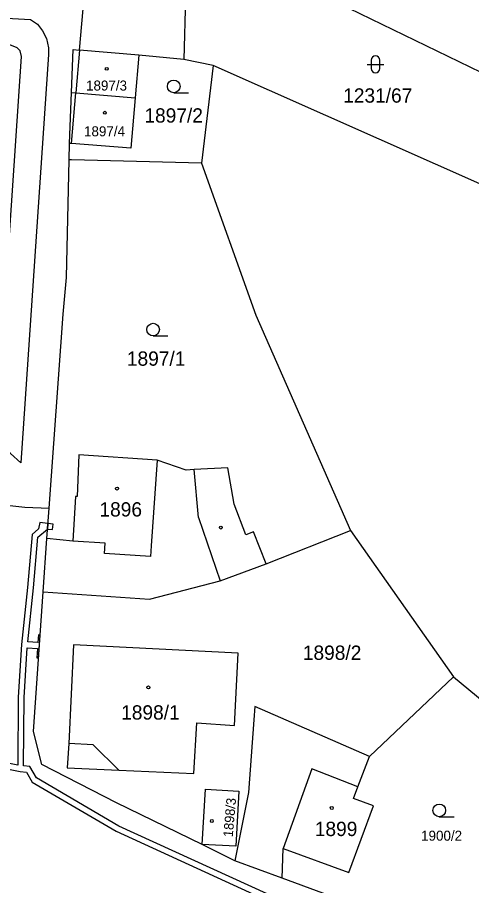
# Model space of a CAD drawing. Extents: x -869103 to -863415, y -1015889 to -1012477.
# Drawn here: x -866081.7 to -866027.8, y -1014098.2 to -1013995 of the extents above; entities that cross this region are included whole.
import ezdxf

# ---------------------------------------------------------------- set-up
doc = ezdxf.new("R2010")
doc.units = 0
for name, color, linetype in [('Hranice parcel', 7, 'Continuous'), ('Parcelní čísla', 7, 'Continuous'), ('Vnitřní kresba', 7, 'Continuous'), ('Věcná břemena k části', 7, 'Continuous'), ('Značky budov', 7, 'Continuous'), ('Značky kultur', 7, 'Continuous')]:
    doc.layers.add(name, color=color, linetype=linetype)

msp = doc.modelspace()

# ---------------------------------------------------------------- linework, layer by layer
at = {"layer": 'Hranice parcel'}
for p, q in [((-866061.52, -1013984.57), (-866061.96, -1014000.03)), ((-866061.52, -1013984.57), (-866023.9, -1014002.91)), ((-866074.34, -1013998.92), (-866073.68, -1013991.28)), ((-866067.3, -1013999.52), (-866074.34, -1013998.92)), ((-866067.3, -1013999.52), (-866067.73, -1014004.57)), ((-866061.96, -1014000.03), (-866067.3, -1013999.52)), ((-866058.47, -1014000.73), (-866061.96, -1014000.03)), ((-866058.47, -1014000.73), (-866059.85, -1014012.35)), ((-866019.25, -1014018.15), (-866058.47, -1014000.73)), ((-866075.52, -1014010.01), (-866075.29, -1014003.97)), ((-866075.29, -1014003.97), (-866074.78, -1014004.01)), ((-866074.78, -1014004.01), (-866067.73, -1014004.57)), ((-866075.57, -1014011.96), (-866075.52, -1014010.01)), ((-866075.3, -1014010.03), (-866075.52, -1014010.01)), ((-866077.96, -1014053.35), (-866076.3, -1014030.31)), ((-866084.83, -1014052.8), (-866080.86, -1014053.22)), ((-866080.86, -1014053.22), (-866077.96, -1014053.35)), ((-866078.22, -1014056.97), (-866077.96, -1014053.35)), ((-866052.18, -1014059.97), (-866042.17, -1014056.01)), ((-866042.17, -1014056.01), (-866029.91, -1014073.39)), ((-866078.65, -1014063.29), (-866078.22, -1014056.97)), ((-866029.91, -1014073.39), (-866039.91, -1014082.84)), ((-866029.91, -1014073.39), (-866022.28, -1014079.75)), ((-866041.28, -1014086.47), (-866039.91, -1014082.84)), ((-866050.27, -1014097.31), (-866050.15, -1014093.78)), ((-866050.15, -1014093.78), (-866042.37, -1014096.65)), ((-866050.27, -1014097.31), (-866055.88, -1014095.24))]:
    msp.add_line(p, q, dxfattribs=at)
for points in [[(-866086.37, -1013994.34), (-866086.2, -1013994.7), (-866085.86, -1013994.95), (-866080.16, -1013995.28), (-866079.34, -1013995.84), (-866078.76, -1013996.61), (-866078.28, -1013997.55), (-866078.04, -1013998.64), (-866078.04, -1013999.43), (-866081.32, -1014047.95), (-866082.54, -1014046.85), (-866083.4, -1014046.21), (-866084.37, -1014045.66), (-866081.25, -1013999.67), (-866081.41, -1013999.02), (-866081.75, -1013998.65), (-866082.62, -1013998.29), (-866090.88, -1013997.79), (-866094.03, -1013993.9)], [(-866075.29, -1014003.97), (-866075.1, -1013998.86), (-866074.34, -1013998.92)], [(-866067.73, -1014004.57), (-866068.24, -1014010.55), (-866075.3, -1014010.03)], [(-866076.3, -1014030.31), (-866075.89, -1014025.95), (-866075.57, -1014011.96)], [(-866059.85, -1014012.35), (-866075.3, -1014011.97), (-866075.57, -1014011.96)], [(-866059.85, -1014012.35), (-866053.39, -1014030.4), (-866042.17, -1014056.01)], [(-866065.12, -1014047.66), (-866074.42, -1014047.01), (-866074.61, -1014051.97), (-866074.81, -1014051.96), (-866075.12, -1014057.26), (-866078.22, -1014056.97)], [(-866052.18, -1014059.97), (-866053.68, -1014056.17), (-866054.6, -1014056.53), (-866055.98, -1014052.86), (-866056.71, -1014048.57), (-866060.72, -1014048.77), (-866061.69, -1014048.82), (-866065.12, -1014047.66)], [(-866078.65, -1014063.29), (-866066.03, -1014064.14), (-866057.64, -1014061.97), (-866052.18, -1014059.97)], [(-866055.88, -1014095.24), (-866059.78, -1014093.3), (-866069.96, -1014088.36), (-866078.83, -1014083.8), (-866079.8, -1014079.9), (-866078.65, -1014063.29)], [(-866060.43, -1014078.84), (-866055.94, -1014079.17), (-866055.5, -1014070.59), (-866075.06, -1014069.59), (-866075.63, -1014081.32), (-866075.8, -1014084.2), (-866069.66, -1014084.49), (-866060.76, -1014084.89), (-866060.43, -1014078.84)], [(-866039.91, -1014082.84), (-866053.54, -1014076.93), (-866053.65, -1014078.48)], [(-866053.65, -1014078.48), (-866054.28, -1014087.14), (-866055.88, -1014095.24)], [(-866055.42, -1014086.97), (-866055.78, -1014093.52), (-866059.78, -1014093.3), (-866059.4, -1014086.73), (-866055.42, -1014086.97)], [(-866042.37, -1014096.65), (-866039.44, -1014088.71), (-866041.81, -1014087.83), (-866041.28, -1014086.47)], [(-866018.26, -1014107.1), (-866024.51, -1014106.26), (-866028.71, -1014105.27), (-866050.27, -1014097.31)]]:
    msp.add_lwpolyline(points, dxfattribs=at)
at = {"layer": 'Vnitřní kresba'}
for p, q in [((-866074.34, -1013998.92), (-866074.78, -1014004.01)), ((-866075.3, -1014010.03), (-866074.78, -1014004.01)), ((-866065.12, -1014047.66), (-866065.84, -1014057.81)), ((-866060.22, -1014054.45), (-866060.72, -1014048.77)), ((-866060.22, -1014054.45), (-866057.64, -1014061.97)), ((-866071.31, -1014057.49), (-866075.12, -1014057.26)), ((-866071.38, -1014058.73), (-866071.31, -1014057.49)), ((-866065.84, -1014057.81), (-866065.92, -1014059.08)), ((-866065.92, -1014059.08), (-866071.38, -1014058.73)), ((-866072.74, -1014081.45), (-866075.63, -1014081.32)), ((-866069.66, -1014084.49), (-866072.74, -1014081.45)), ((-866046.75, -1014084.34), (-866050.15, -1014093.78)), ((-866041.28, -1014086.47), (-866046.75, -1014084.34))]:
    msp.add_line(p, q, dxfattribs=at)
at = {"layer": 'Věcná břemena k části'}
for points in [[(-866052.07, -1014099.17), (-866069.66, -1014091.12), (-866079.44, -1014085.4), (-866080.24, -1014084.05), (-866080.98, -1014083.98), (-866080.92, -1014075.83), (-866080.55, -1014069.94), (-866079.33, -1014070.02), (-866079.42, -1014071.14), (-866079.2, -1014071.17), (-866079.01, -1014068.43), (-866079.21, -1014068.41), (-866079.28, -1014069.32), (-866080.49, -1014069.24), (-866079.83, -1014062.82), (-866079.29, -1014056.8), (-866078.14, -1014055.85), (-866078.09, -1014055.17), (-866079.06, -1014055.05), (-866079.2, -1014055.79), (-866079.97, -1014056.46), (-866080.53, -1014062.76), (-866081.23, -1014069.53), (-866081.62, -1014075.81), (-866081.68, -1014083.88), (-866086.03, -1014083.02)], [(-866138.85, -1014099.9), (-866126.98, -1014101.57), (-866123.49, -1014101.89), (-866116.37, -1014102.66), (-866092.66, -1014105.81), (-866088.56, -1014106.7), (-866088.26, -1014107.08), (-866088.42, -1014110.08), (-866088.97, -1014110.12), (-866089.05, -1014110.81), (-866088.22, -1014110.98), (-866087.64, -1014110.46), (-866087.46, -1014106.98), (-866087.55, -1014106.39), (-866088.27, -1014105.23), (-866087.8, -1014100.67), (-866087.07, -1014093.57), (-866086.3, -1014084.23), (-866085.81, -1014083.78), (-866081.38, -1014084.65), (-866080.66, -1014084.71), (-866079.96, -1014085.92), (-866069.98, -1014091.74), (-866051.77, -1014100.07)]]:
    msp.add_lwpolyline(points, dxfattribs=at)
msp.add_lwpolyline([(-866078.09, -1014055.17), (-866078.14, -1014055.85), (-866077.54, -1014055.88), (-866077.49, -1014055.25)], close=True, dxfattribs=at)
at = {"layer": 'Značky budov'}
for centre in [(-866071.11, -1014001.14), (-866071.34, -1014006.36), (-866069.89, -1014051.02), (-866057.56, -1014055.65), (-866066.17, -1014074.65), (-866044.39, -1014088.97), (-866058.63, -1014090.52)]:
    msp.add_circle(centre, 0.175, dxfattribs=at)
at = {"layer": 'Značky kultur'}
for p, q in [((-866040.19, -1014000.61), (-866038.19, -1014000.61)), ((-866039.69, -1014000.11), (-866039.69, -1014001.11)), ((-866038.69, -1014001.11), (-866038.69, -1014000.11)), ((-866063.15, -1014003.98), (-866061.4, -1014003.98)), ((-866065.6, -1014032.87), (-866063.85, -1014032.87)), ((-866031.61, -1014090.01), (-866029.86, -1014090.01))]:
    msp.add_line(p, q, dxfattribs=at)
for centre in [(-866063.15, -1014003.23), (-866065.6, -1014032.12), (-866031.61, -1014089.26)]:
    msp.add_circle(centre, 0.75, dxfattribs=at)
for centre, start, end in [((-866039.19, -1014000.11), 0, 180), ((-866039.19, -1014001.11), 180, 359.9879)]:
    msp.add_arc(centre, 0.5, start, end, dxfattribs=at)

# ---------------------------------------------------------------- texts
at = {"layer": 'Parcelní čísla'}
for s, height, p in [('1897/3', 1.19, (-866073.57, -1014003.72)), ('1231/67', 1.7, (-866043.03, -1014005.16)), ('1897/2', 1.7, (-866066.64, -1014007.53)), ('1897/4', 1.19, (-866073.81, -1014009.16)), ('1897/1', 1.7, (-866068.72, -1014036.42)), ('1896', 1.7, (-866071.98, -1014054.34)), ('1898/2', 1.7, (-866047.82, -1014071.37)), ('1898/1', 1.7, (-866069.4, -1014078.47)), ('1899', 1.7, (-866046.4, -1014092.31)), ('1900/2', 1.19, (-866033.77, -1014092.86))]:
    msp.add_text(s, height=height, dxfattribs=at).set_placement(p)
msp.add_text('1898/3', height=1.139, rotation=85, dxfattribs=at).set_placement((-866056.15, -1014092.47))

doc.saveas('drawing.dxf')
